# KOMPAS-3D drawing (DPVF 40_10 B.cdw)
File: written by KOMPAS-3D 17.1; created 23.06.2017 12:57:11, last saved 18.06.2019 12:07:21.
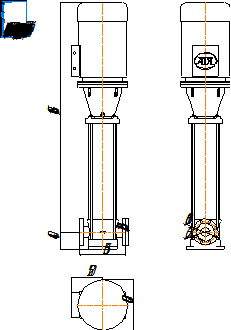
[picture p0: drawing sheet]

Sheet 1: A4, portrait

Title block, sheet 1: name: DPVF 40_10 B; material: Внимание! Данный продукт является объектом авторского права ООО «Торговый Дом АДЛ». / Запрещается изменение, копирование, распространение / (в том числе путем копирования на другие сайты и ресурсы в Интернете) / или любое иное использование информации и объектов без предварительного / согласия правообладателя (ООО «Торговый Дом АДЛ»).; scale: 1:1; sheets: 1; organisation: ООО "Торговый дом АДЛ"; sheet format: A4; stored path: C:\Клочков АВ\Насосы\DP PAMS\DPVF 40\Компас 2d\DPVF 40_10 B.cdw

Views: Спереди 1
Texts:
  Клочков АВ
  ООО АДЛ ГРУПП
Dimensions and other numbers on the sheet: 365; 250; 400; 209,6; 1819,5; 140; 168,1; 76,2; 1:1; 1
